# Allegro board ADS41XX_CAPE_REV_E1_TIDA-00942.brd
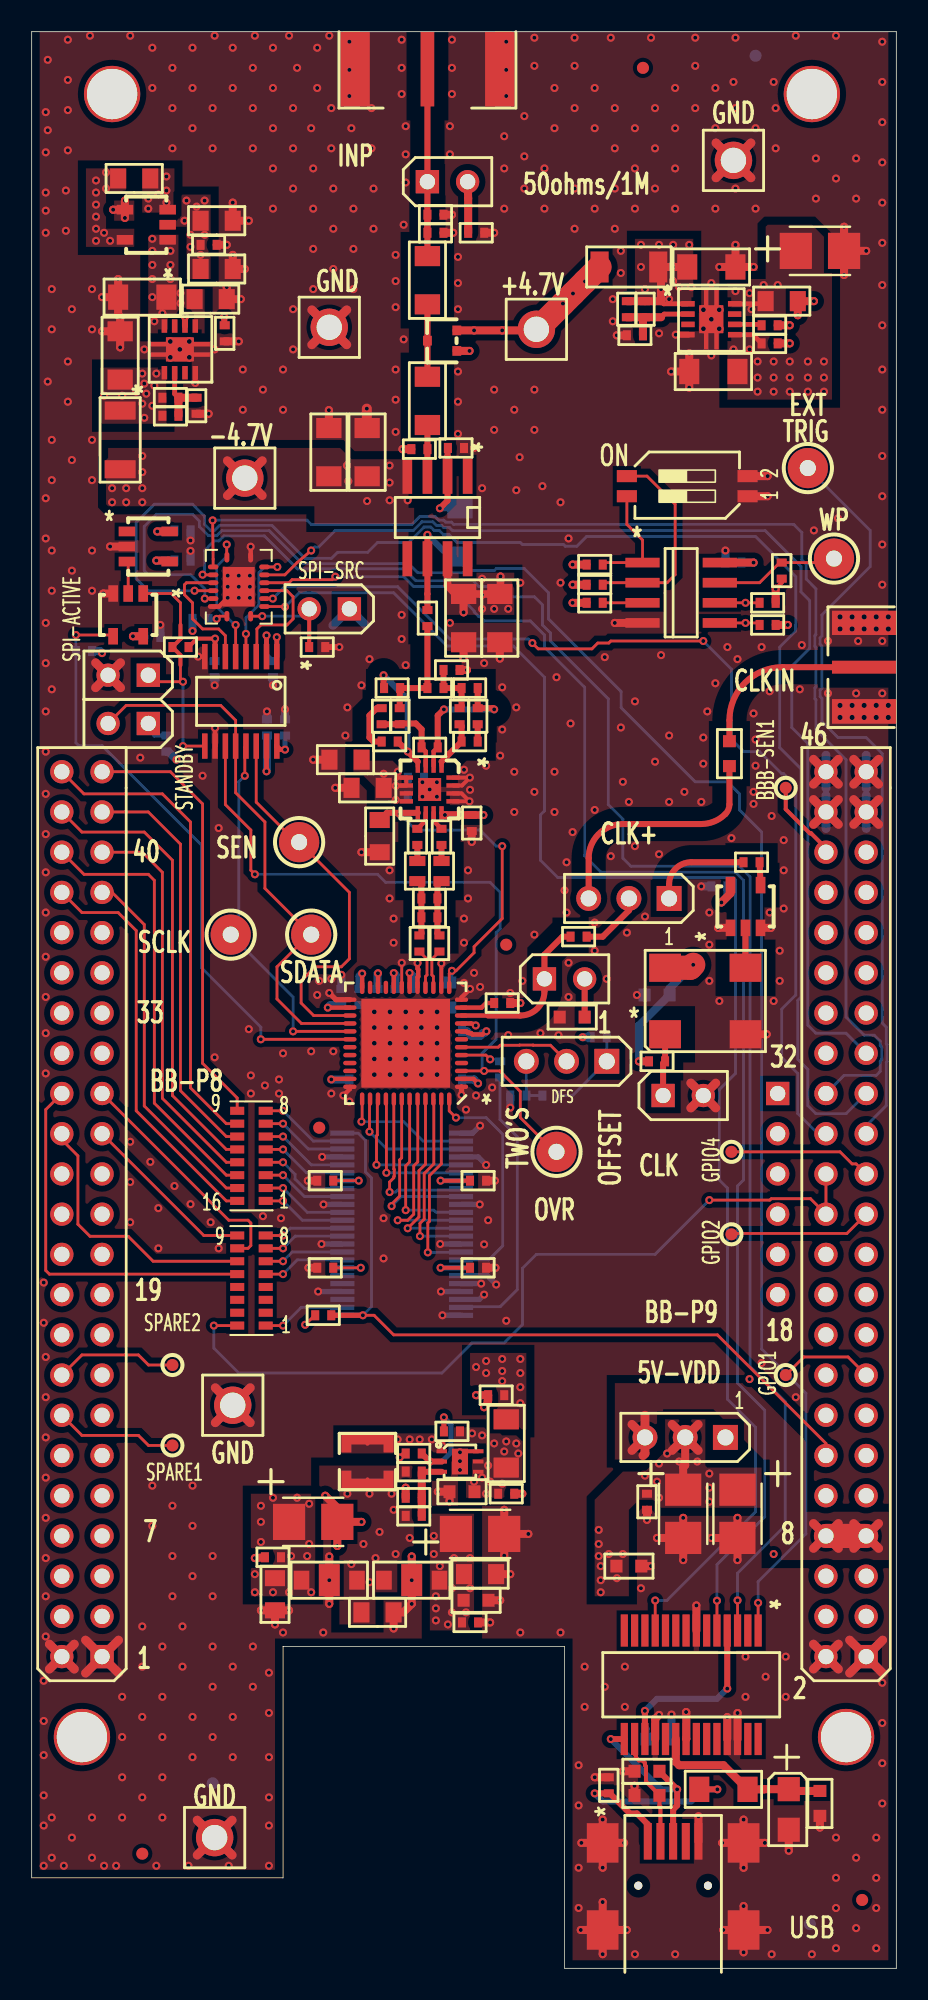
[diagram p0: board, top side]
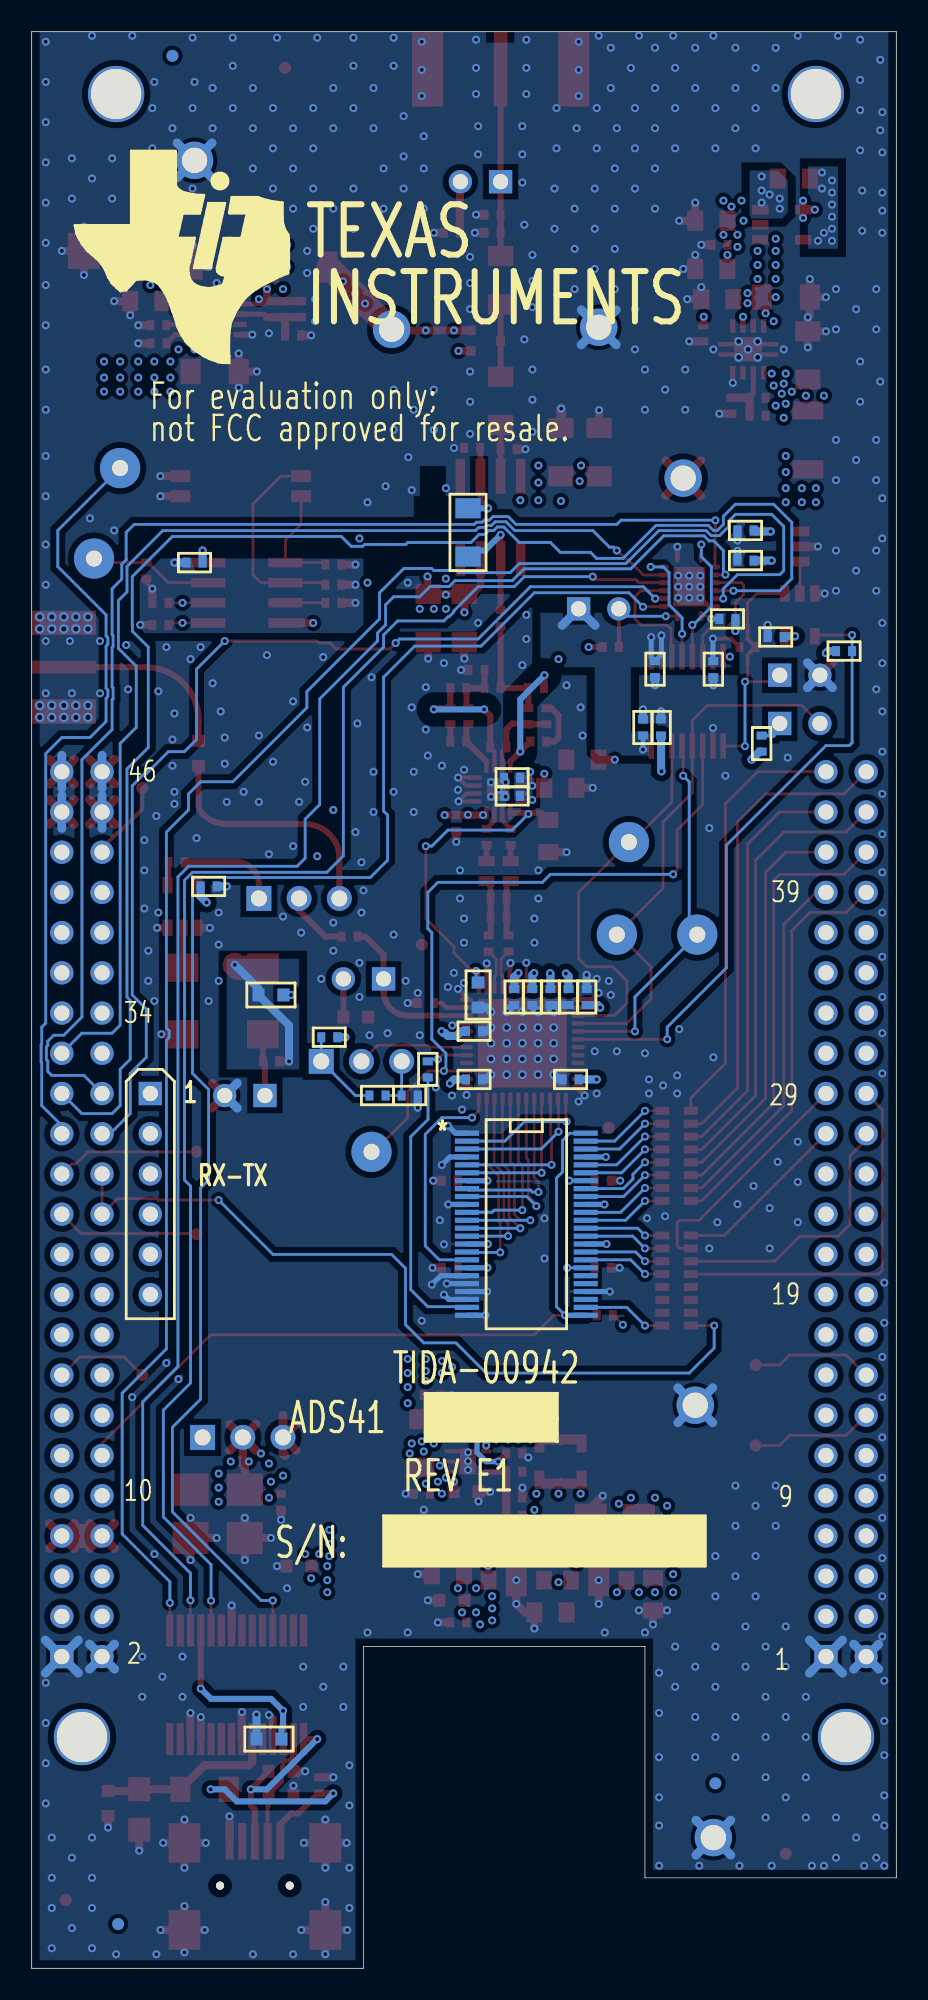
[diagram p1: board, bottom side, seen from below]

Outline 54.61 x 122.3 mm; copper layers: TOP, GND1, PWR1, PWR2, GND2, BOTTOM. Coordinates in mm from the lower left corner of the outline.
Outline path: 0,122.3 0,5.71 15.88,5.71 15.88,20.32 33.66,20.32 33.66,0 54.61,0 54.61,122.3 0,122.3

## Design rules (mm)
net group B: nets B+ B-
net group CLK: nets CLK+ CLK-
net group IN: nets IN_M IN_P
net group PWR: nets N18756762 N18756812

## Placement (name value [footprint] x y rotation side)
C1  82pF  [0402]  25.5 80.85 0 top
C2  12pF  [0402]  28.17 79.07 270 top
C3  5.6pF  [0402]  25.14 77.1 0 top
C4  10uF  [0805]  21.22 74.55 180 top
C5  .1uF  [0805]  19.82 76.33 180 top
C6  .1uF  [0402]  24.27 75.18 0 bottom
C7  .1uF  [0402]  24.27 74.04 0 bottom
C8  .1uF  [0402]  34.54 65.15 180 top
C9  .1uF  [0402]  43.43 68.33 0 bottom
C10  .1uF  [0402]  29.72 60.96 0 top
C11  5pF  [0402]  24.49 95.94 180 top
C12  0.1uF  [0603]  39.5 61.47 180 bottom
C13  .01uF  [0402]  26.67 59.18 180 bottom
C14  .01uF  [0402]  24.13 61.34 270 bottom
C15  .01uF  [0402]  19.56 61.34 90 bottom
C16  .01uF  [0402]  20.7 61.34 270 bottom
C17  .01uF  [0402]  21.84 61.34 270 bottom
C18  .01uF  [0402]  22.99 61.34 270 bottom
C19  .01uF  [0402]  20.57 56.13 0 bottom
C20  .01uF  [0402]  26.67 56.13 180 bottom
C21  0.1uF  [0603]  26.42 61.47 270 bottom
C22  .01uF  [0402]  15.24 82.04 270 bottom
C23  .01uF  [0402]  36.45 11.56 90 top
C24  0.1uF  [0603]  49.78 10.41 270 top
C25  4.7uF  [TANT_A]  47.82 10.03 270 top
C26  47pF  [0603]  38.86 10.92 180 top
C27  47pF  [0603]  38.86 12.45 180 top
C28  0.1uF  [0603]  39.62 14.48 0 bottom
C29  .01uF  [0402]  18.54 44.24 180 top
C30  .01uF  [0402]  18.54 49.74 180 top
C31  .01uF  [0402]  28.19 44.24 0 top
C32  .01uF  [0402]  28.19 49.74 0 top
C33  47uF  [TANT_B]  44.58 28.7 270 top
C34  10uF  [TANT_B]  41.15 28.7 270 top
C35  .1uF  [0402]  38.86 29.46 270 top
C36  1uF  [0603]  37.72 25.4 0 top
C38  .1uF  [0402]  29.34 36.2 180 top
C39  .01uF  [0402]  29.97 29.97 0 top
C40  1uF  [0603]  27.18 30.1 180 top
C41  22pF  [0402]  24.13 28.57 0 top
C42  10uF  [0805]  21.84 22.48 0 top
C43  33uF  [TANT_B]  28.32 27.43 0 top
C44  10uF  [0805]  28.32 24.89 0 top
C45  2.2uF  [0603]  28.07 23.24 0 top
C46  .1uF  [0402]  27.69 21.84 0 top
C48  33uF  [TANT_B]  17.78 28.19 0 top
C49  10uF  [0805]  15.37 23.62 270 top
C50  .1uF  [0402]  15.24 25.96 180 top
C51  .01uF  [0402]  11.56 82.04 270 bottom
C52  10uF  [TANT_B]  49.78 108.46 0 top
C53  .01uF  [0402]  16 78.36 90 bottom
C54  .01uF  [0402]  14.86 78.36 90 bottom
C56  680pF  [0402]  25.12 66.37 0 top
C57  .1uF  [1206]  21.18 95.75 90 top
C58  .1uF  [1206]  27.28 85.27 270 top
C59  6.8uF  [1206]  18.77 95.75 90 top
C60  6.8uF  [1206]  29.57 85.27 270 top
C61  .1uF  [0402]  44.32 88.77 180 bottom
C62  10pF  [0402]  25.5 110.74 0 top
C71  .1uF  [0402]  27.79 72.33 270 top
C75  10uF  [0805]  47.37 105.28 0 top
C76  .1uF  [0402]  46.61 102.62 180 top
C77  10uF  [1206]  43.05 100.84 180 top
C78  10uF  [1206]  42.93 107.44 0 top
C79  .01uF  [0402]  38.73 104.78 270 top
C80  .01uF  [0402]  46.61 103.76 0 top
C82  10uF  [0805]  11.68 107.31 0 top
C83  .1uF  [0402]  11.18 108.84 180 top
C84  1uF  [0805]  11.68 110.36 0 top
C86  10uF  [1206]  6.99 105.54 180 top
C87  10uF  [1206]  5.59 101.85 90 top
C88  .01uF  [0402]  8.76 99.19 0 top
C89  1uF  [0402]  12.19 103.25 270 top
C90  1uF  [0805]  11.3 105.41 0 top
C91  1uF  [0805]  6.48 113.03 0 top
C98  .1uF  [0805]  21.98 71.5 270 top
C99  12pF  [0402]  22.1 79.07 90 top
C101  .01uF  [0402]  10.67 85.22 180 bottom
C102  .01uF  [0402]  7.62 84.07 0 bottom
C103  .1uF  [0402]  9.53 88.9 0 bottom
C104  1uF  [0402]  9.53 90.81 0 bottom
D1  BAV99W  [SOT_323]  25.92 102.79 90 top
FB1  120 OHM @ 100MHz  [1206]  43.69 11.3 0 top
FB3  27uF  [1206_BEAD_NFM31P]  24 24.51 0 top
FB4  27uF  [1206_BEAD_NFM31P]  18.8 24.51 180 top
FB5  120 OHM @ 100MHz  [1206]  29.97 33.15 270 top
FB6  1k @ 100MHz  [1806]  37.72 107.44 0 top
FB7  1k @ 100MHz  [1806]  5.59 96.52 90 top
J1  BNC, HIGH FREQ, END LAUNCH  [BNC_END_LAUNCH_50_OHM_112640]  24.99 122.3 0 top
J2  HDR, THVT, 6POS, .100, FEMALE  [HDR_THVT_1X6_100_M]  47.12 55.24 180 bottom
J3  SMA_END_JACK_RND  [SMA_SMEL_250X215]  54.61 82.17 270 top
J4  USB, MINI_AB  [CON_SMRT_USBMNE20_F]  40.51 4.57 90 top
J5  HDR, THVT, 46POS, .100, FEMALE  [HDR_THVT_2X23_100_M]  4.45 19.68 180 top
J6  HDR, THVT, 46POS, .100, FEMALE  [HDR_THVT_2X23_100_M]  52.7 19.68 180 top
JP1  HEADER, 2POS, .100  [HDR_THVT_1X2_100_M]  7.37 78.61 270 top
JP2  HEADER, 2POS, .100  [HDR_THVT_1X2_100_M]  20.07 85.85 270 top
JP3  HEADER, 2POS, .100  [HDR_THVT_1X2_100_M]  7.37 81.66 270 top
JP4  HEADER, 3POS, .100  [HDR_THVT_1X3_100_M]  43.81 33.53 270 top
JP5  HEADER, 2POS, .100  [HDR_THVT_1X2_100_M]  24.99 112.83 90 top
JP6  HEADER, 3POS, .100  [HDR_THVT_1X3_100_M]  36.32 57.28 270 top
JP7  HEADER, 2POS, .100  [HDR_THVT_1X2_100_M]  39.88 55.12 90 top
JP8  HEADER, 3POS, .100  [HDR_THVT_1X3_100_M]  40.26 67.56 270 top
JP9  HEADER, 2POS, .100  [HDR_THVT_1X2_100_M]  32.38 62.48 90 top
L1  2.2uH  [LPS3015]  21.21 32 270 top
L2  390nH  [IND_0603]  24.36 69.29 270 top
L3  390nH  [IND_0603]  25.88 69.29 270 top
MT1  STANDOFF, FEMALE, 4-40 X 3/4"  [MFG125_PLATED]  5.08 118.36 0 top
MT2  STANDOFF, FEMALE, 4-40 X 3/4"  [MFG125_PLATED]  49.28 118.36 0 top
MT3  STANDOFF, FEMALE, 4-40 X 3/4"  [MFG125_PLATED]  3.17 14.61 0 top
MT4  STANDOFF, FEMALE, 4-40 X 3/4"  [MFG125_PLATED]  51.44 14.61 0 top
NOREF  -  []  54.61 0 90 top
NOREF#2  -  []  15.88 5.71 0 top
NOREF#3  -  []  33.66 0 0 top
NOREF#4  -  [unnamed#2]  18.16 53.09 0 top
NOREF#5  -  []  0 5.71 90 top
NOREF#6  -  []  -52.2 -70.97 0 top
NOREF#7  -  []  0 5.71 0 top
NOREF#8  -  []  475.87 104.42 0 top
NOREF#9  -  [unnamed#2]  38.61 120.02 0 top
NOREF#10  -  [unnamed#2]  29.97 64.64 0 top
NOREF#11  -  []  33.66 0 90 top
NOREF#12  -  [unnamed#2]  6.99 7.24 0 top
NOREF#13  -  []  0 5.71 90 top
NOREF#14  -  [unnamed#2]  52.45 4.32 0 top
NOREF#15  -  []  205.61 62.97 0 top
NOREF#16  -  []  3.17 14.61 0 top
NOREF#17  -  []  54.61 0 90 top
NOREF#18  -  []  33.66 0 90 top
NOREF#19  -  []  51.44 14.61 0 top
NOREF#20  -  []  39.37 26.04 180 bottom
NOREF#21  -  [unnamed#2]  49.15 2.79 180 bottom
NOREF#22  -  []  43.83 108.62 180 bottom
NOREF#23  -  [unnamed#2]  45.72 120.78 180 bottom
NOREF#24  -  []  36.82 33.85 180 bottom
NOREF#25  -  [unnamed#2]  11.43 11.68 180 bottom
NOREF#26  -  []  105.16 78.11 180 bottom
PP1  PROBE POINT  [PROBE_POINT_30PAD]  47.62 37.47 0 top
PP2  PROBE POINT  [PROBE_POINT_30PAD]  44.2 51.56 0 top
PP3  PROBE POINT  [PROBE_POINT_30PAD]  44.2 46.35 0 top
PP4  PROBE POINT  [PROBE_POINT_30PAD]  8.89 38.1 0 top
PP5  PROBE POINT  [PROBE_POINT_30PAD]  8.89 33.02 0 top
PP6  PROBE POINT  [PROBE_POINT_30PAD]  47.62 74.55 0 top
R1  27.4  [0402]  24.36 71.45 270 top
R2  8.25  [0402]  22.61 77.47 0 top
R3  27.4  [0402]  25.88 71.45 270 top
R4  8.25  [0402]  27.66 77.47 180 top
R5  348  [0402]  23.25 79.07 270 top
R6  348  [0402]  27.66 80.85 0 top
R7  221  [0402]  27.03 79.07 270 top
R8  392  [0402]  24.99 85.27 270 top
R9  49.9  [1206]  24.99 98.98 270 top
R10  150  [1206]  24.99 106.6 270 top
R11  392  [0402]  26.52 81.99 0 top
R12  649k  [0402]  8.76 98.04 0 top
R13  215k  [0402]  10.41 98.68 270 top
R14  442  [0402]  25.12 67.56 180 top
R15  5.6k  [0402]  46.48 84.84 180 top
R16  200  [1206]  27.05 90.68 270 bottom
R17  221  [0402]  22.76 80.85 180 top
R18  0  [0603]  44.07 76.71 270 top
R19  2k  [0402]  32.77 55.12 180 bottom
R20  5.6k  [0402]  46.48 86.23 180 top
R21  49.9  [0603]  34.14 60.07 180 top
R22  4.75k  [0402]  35.56 86.23 0 top
R23  4.75k  [0402]  35.56 87.38 0 top
R24  10k  [0402]  39.5 57.28 0 top
R25  49.9  [0402]  45.47 69.85 180 top
R26  4.75k  [0402]  35.56 88.65 0 top
R27  22.1  [0402]  29.59 56.77 90 bottom
R30  3k  [0402]  35.81 58.8 0 bottom
R31  0  [0402]  24.13 32.51 180 top
R32  3k  [0402]  30.73 55.12 180 bottom
R41  4.7k  [0402]  18.41 41.24 0 top
R42  0  [0402]  26.54 33.91 180 top
R44  360k  [0402]  24.13 31.37 0 top
R46  180k  [0402]  24.13 29.72 180 top
R53  5.1  [0402]  24.49 64.72 270 top
R54  5.1  [0402]  25.76 64.72 270 top
R55  49.9  [0402]  28.08 109.6 0 top
R56  1M  [0402]  25.5 109.6 180 top
R57  249  [0402]  26.8 96.01 0 top
R83  34.8k  [0402]  37.59 104.78 270 top
R84  12k  [0402]  38.1 103.12 180 top
R85  10k  [0402]  18.03 83.44 0 top
R86  10k  [0402]  9.4 83.44 180 top
R87  10k  [0402]  8.51 77.34 90 bottom
R88  10k  [0402]  3.3 83.19 180 bottom
R89  10k  [0402]  47.37 88.27 90 top
RN1  22  [RNET8_16_0603]  15.75 52.96 180 top
RN2  22  [RNET8_16_0603]  15.75 45.09 180 top
SW1  SWITCH, ULTRA MINI  [SW_SM_2POS_144X244_50_TDA]  41.4 93.6 90 top
TP3  BLU  [TP_THVT_100_RND]  33.15 51.56 0 top
TP8  BLK  [TP_THVT_125_RND_063D]  11.56 8.26 0 top
TP9  BLK  [TP_THVT_125_RND_063D]  12.7 35.56 0 top
TP10  RED  [TP_THVT_125_RND_063D]  31.88 103.5 0 top
TP11  RED  [TP_THVT_125_RND_063D]  13.46 94.11 0 top
TP12  BLU  [TP_THVT_100_RND]  49.02 94.74 0 top
TP13  BLK  [TP_THVT_125_RND_063D]  44.32 114.17 0 top
TP14  BLK  [TP_THVT_125_RND_063D]  18.8 103.63 0 top
TP15  BLU  [TP_THVT_100_RND]  16.89 71.12 0 top
TP16  BLU  [TP_THVT_100_RND]  12.57 65.28 0 top
TP17  BLU  [TP_THVT_100_RND]  17.65 65.28 0 top
TP18  BLU  [TP_THVT_100_RND]  50.67 89.03 0 top
U1  ADS4122  [QFN_48_281X281_0P50MM_RGZ]  23.62 58.42 180 top
U2  FT245RL  [SSOP_28_413X221_26]  41.66 17.91 270 top
U3  SN74AVC16T245DGGR  [TSSOP_48_496X244_20]  23.37 46.99 180 bottom
U4  TPS62590  [SON_DRV_6]  27.05 32 0 top
U5  THS4541  [VQFN_16_124X124_PWRPAD]  25.14 74.45 270 top
U6  OPA656NB  [SO_8_197X157_50]  25.63 91.62 270 top
U7  TPS7A4901  [SON_8_3MMX3MM_0P65MM]  42.93 104.14 0 top
U8  TPS60403  [SOT-23_5_63X114_DBV]  7.24 110.11 180 top
U9  TPS7A3001  [SON_8_3MMX3MM_0P65MM]  9.36 102.24 90 top
U10  SN74AVC4T774  [TSSOP_16_201X177_26]  13.21 80.01 270 top
U11  SN74CB3Q3257  [VQFN_16_163X144_0P50MM_RGY]  13.08 87.25 270 top
U12  TPS3125J18  [SOT-23_5_63X114_DBV]  7.37 89.79 0 top
U13  SN74AUC1G125  [SOT-23_5_63X114_DBV]  6.1 85.47 270 top
U14  SN74AUC1G125  [SOT-23_5_63X114_DBV]  45.09 67.06 90 top
U15  CAT24C256W  [SOIC_8_197X157_50]  41.02 86.87 0 top
Y1  20.000MHz  [OSC_4_SM_295X197]  42.55 61.09 0 top

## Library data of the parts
C1 = CAP_0402_82pF
C2 C3 C99 = CAP_0402_5.6pF
C4 = CAP_0805_10uF_16V: tolerance: 10%, 10V, X7R
C5 = CAP_0805_.1uF_16V: tolerance: 10%, 50V, X7R
C6 C7 C10 C35 C38 C46 C50 C61 C71 C103 = CAP_0402_0.1uF
C8 C9 = CAP_0402_0.1uF_H
C11 = CAP_0402_5pF
C12 C21 C24 C28 = CAP_0603_0.1uF
C13-C20 C22 C23 C29-C32 C39 C51 C53 C54 C79 C80 C88 C101 C102 = CAP_0402_0.01uF
C25 = CAP_TANT_A_4.7uF
C26 C27 = CAP_0603_47pF
C33 = CAP_TANT_B_47uF
C34 C52 = CAP_TANT_B_10uF_10V: tolerance: 20%
C36 C40 = CAP_0603_1uF
C41 = CAP_0402_22pF
C42 C44 C49 = CAP_0805_10uF_10V
C43 C48 = CAP_TANT_B_33uF
C45 = CAP_0603_2.2uF
C56 = CAP_0402_680pF
C57 C58 = CAP_1206_.1uF
C59 C60 = CAP_1206_6.8uF
C62 = CAP_0402_10pF
C75 C82 = CAP_1206_2.2uF: tolerance: 10%
C76 C83 = CAPACITOR_NP_1: tolerance: 10%
C77 C78 C86 C87 = CAP_1206_10uF
C84 C90 C91 = CAP_0805_1uF_16V: tolerance: 10%, 25V, X5R
C89 C104 = CAP_0402_1uF
C98 = CAP_0805_0.1uF_HF_10V: tolerance: 5%
D1 = DIODE_DUAL_BAV99W
FB1 FB5 = FERRITE_BEAD_1206_120_H
FB3 FB4 = BEAD_NFM31P
FB6 FB7 = FERRITE_BEAD
J1 = BNC_END_LAUNCH_SMT_112640
J2 = HEADER_1x6_100
J3 = TMP_102603
J4 = USB_MINI_AB_MNE20-5G5P10
J5 J6 = HEADER_2x23_100
JP1-JP3 JP5 JP7 JP9 = JUMPER_1X2_100
JP4 JP6 JP8 = JUMPER_1X3_100
L1 = IND1206_0
L2 L3 = IND_0603_H_0
MT1-MT4 = MOUNTING_HOLE
PP1-PP6 = PROBE_POINT_0
R1 R3 = Res_0402_80.6_H
R2 R4 = Res_0402_8.25: tolerance: 1%
R5 R6 = Res_0402_348
R7 R17 = Res_0402_221
R8 R11 = Res_0402_392
R9 = Res_1206_49.9_.1%: tolerance: .1%
R10 = Res_1206_150: tolerance: 1%
R12 = Res_0402_649k
R13 = Res_0402_215k
R14 = Res_0402_442_H
R15 R20 = Res_0402_5.6K
R16 = Res_1206_200_.1%: tolerance: .1%
R18 = Res_0603_Zero_H
R19 = Res_0402_2K
R21 = RES0603: tolerance: 1%
R22 R23 R26 = Res_0402_4.75k
R24 R85-R89 = Res_0402_10k
R25 = Res_0402_49.9_H
R27 = Res_0402_22.1_H
R30 R32 = Res_0402_3k
R31 = Res_0402_Zero_DNI
R41 = Res_0402_4.7k
R42 = Res_0402_Zero
R44 = Res_0402_360K
R46 = Res_0402_180K
R53 R54 = Res_0402_5.1_H
R55 = Res_0402_49.9
R56 = Res_0402_1M_H
R57 = Res_0402_249_.1%: tolerance: .1%
R83 = Res_0402_34.8k: tolerance: .1%
R84 = Res_0402_12k: tolerance: .1%
RN1 RN2 = R-PACK: tolerance: 5%
SW1 = SW_SM_ULTRA_MINI_TDA02H0SB1
TP3 TP12 TP15-TP18 = TESTPOINT_BLUE
TP8 TP9 TP13 TP14 = TESTPOINT_BLK
TP10 TP11 = TESTPOINT_RED
U1 = ADS412X-VQFN
U2 = FT245RL_0
U3 = SN74AVC16T245DGGR_0
U4 = TPS79633DCQ_3
U5 = THS4541_VQFN
U6 = OPA656UB
U7 = TPS7A49
U8 = TPS6040x
U9 = TPS7A30
U10 = SN74AVC4T774
U11 = SN74CB3Q3257
U12 = TPS3125-XX
U13 U14 = SN74AUC1G125
U15 = CAT24C256W
Y1 = OSC_SM_4_FXO-HC73

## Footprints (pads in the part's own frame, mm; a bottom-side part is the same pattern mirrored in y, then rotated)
0402
  rect 0.508x0.635 smd: 1(-0.508,0) 2(0.508,0)
0603
  rect 0.762x0.813 smd: 1(-0.787,0) 2(0.787,0)
0805
  rect 1.016x1.27 smd: 1(-1.016,0) 2(1.016,0)
1206
  rect 1.27x1.6 smd: 1(-1.524,0) 2(1.524,0)
1206_BEAD_NFM31P
  rect 0.991x1.194 smd: 1(-1.753,0) 3(1.753,0)
  rect 1.321x2.032 smd: 2(0,0)
1806
  rect 1.143x1.956 smd: 1(-1.854,0) 2(1.854,0)
BNC_END_LAUNCH_50_OHM_112640
  rect 0.86x4.72 smd: 1(0,-2.36)
  rect 1.35x4.72 smd: 2(-4.925,-2.36) 3(4.925,-2.36)
  rect 1.67x4.72 smd: 4(4.475,-2.36) 5(-4.475,-2.36)
CON_SMRT_USBMNE20_F
  round 0.508 hole 0.991 unplated: (0.65,2.2) (0.65,-2.2)
  rect 2.311x0.508 smd: 1(3.45,1.6) 2(3.45,0.8) 3(3.45,0) 4(3.45,-0.8) 5(3.45,-1.6)
  rect 2.489x2.007 smd: 6(-2.15,-4.45) 7(3.35,-4.45) 8(3.35,4.45) 9(-2.15,4.45)
HDR_THVT_1X2_100_M
  rect 1.473x1.473 hole 0.965: 1(0,0)
  round 1.473 hole 0.965: 2(0,-2.54)
HDR_THVT_1X3_100_M
  rect 1.575x1.575 hole 1.016: 1(0,0)
  round 1.575 hole 1.016: 2(0,-2.54) 3(0,-5.08)
HDR_THVT_1X6_100_M
  rect 1.473x1.473 hole 0.965: 1(0,0)
  round 1.473 hole 0.965: 2(0,-2.54) 3(0,-5.08) 4(0,-7.62) 5(0,-10.16) 6(0,-12.7)
HDR_THVT_2X23_100_M
  rect 1.473x1.473 hole 0.965: 1(0,0)
  round 1.473 hole 0.965: 2(2.54,0) 3(0,-2.54) 4(2.54,-2.54) 5(0,-5.08) 6(2.54,-5.08) 7(0,-7.62) 8(2.54,-7.62) 9(0,-10.16) 10(2.54,-10.16) 11(0,-12.7) 12(2.54,-12.7) 13(0,-15.24) 14(2.54,-15.24) 15(0,-17.78) 16(2.54,-17.78) 17(0,-20.32) 18(2.54,-20.32) 19(0,-22.86) 20(2.54,-22.86) 21(0,-25.4) 22(2.54,-25.4) 23(0,-27.94) 24(2.54,-27.94) 25(0,-30.48) 26(2.54,-30.48) 27(0,-33.02) 28(2.54,-33.02) 29(0,-35.56) 30(2.54,-35.56) 31(0,-38.1) 32(2.54,-38.1) 33(0,-40.64) 34(2.54,-40.64) 35(0,-43.18) 36(2.54,-43.18) 37(0,-45.72) 38(2.54,-45.72) 39(0,-48.26) 40(2.54,-48.26) 41(0,-50.8) 42(2.54,-50.8) 43(0,-53.34) 44(2.54,-53.34) 45(0,-55.88) 46(2.54,-55.88)
IND_0603
  rect 0.635x1.016 smd: 1(-0.635,0) 2(0.635,0)
LPS3015
  custom 0.286x0.286 smd: 1(-1.143,0) 2(1.143,0)
MFG125_PLATED
  round 3.556 hole 3.175: 1(0,0)
OSC_4_SM_295X197
  rect 2.007x1.778 smd: 1(-2.54,-2.101) 2(2.54,-2.101) 3(2.54,2.101) 4(-2.54,2.101)
PROBE_POINT_30PAD
  round 0.762 smd: 1(0,0)
QFN_48_281X281_0P50MM_RGZ
  oval 0.838x0.279 smd: 1(-3.526,2.751) 2(-3.526,2.25) 3(-3.526,1.75) 4(-3.526,1.25) 5(-3.526,0.749) 6(-3.526,0.249) 7(-3.526,-0.249) 8(-3.526,-0.749) 9(-3.526,-1.25) 10(-3.526,-1.75) 11(-3.526,-2.25) 12(-3.526,-2.751) 25(3.526,-2.751) 26(3.526,-2.25) 27(3.526,-1.75) 28(3.526,-1.25) 29(3.526,-0.749) 30(3.526,-0.249) 31(3.526,0.249) 32(3.526,0.749) 33(3.526,1.25) 34(3.526,1.75) 35(3.526,2.25) 36(3.526,2.751)
  oval 0.279x0.838 smd: 13(-2.751,-3.526) 14(-2.25,-3.526) 15(-1.75,-3.526) 16(-1.25,-3.526) 17(-0.749,-3.526) 18(-0.249,-3.526) 19(0.249,-3.526) 20(0.749,-3.526) 21(1.25,-3.526) 22(1.75,-3.526) 23(2.25,-3.526) 24(2.751,-3.526) 37(2.751,3.526) 38(2.25,3.526) 39(1.75,3.526) 40(1.25,3.526) 41(0.749,3.526) 42(0.249,3.526) 43(-0.249,3.526) 44(-0.749,3.526) 45(-1.25,3.526) 46(-1.75,3.526) 47(-2.25,3.526) 48(-2.751,3.526)
  rect 5.601x5.601 smd: 49(0,0)
RNET8_16_0603
  rect 0.889x0.508 smd: 1(0.965,4.496) 2(0.965,3.683) 3(0.965,2.87) 4(0.965,2.057) 5(0.965,1.245) 6(0.965,0.432) 7(0.965,-0.381) 8(0.965,-1.194) 9(2.769,-1.194) 10(2.769,-0.381) 11(2.769,0.432) 12(2.769,1.245) 13(2.769,2.057) 14(2.769,2.87) 15(2.769,3.683) 16(2.769,4.496)
SMA_SMEL_250X215
  rect 0.813x4.064 smd: 1(0,-2.032)
  rect 1.524x4.064 smd: 2(-2.794,-2.032) 3(2.794,-2.032) 4(-2.794,-2.032) 5(2.794,-2.032)
SO_8_197X157_50
  rect 2.21x0.61 smd: 1(-2.603,1.905) 2(-2.603,0.635) 3(-2.603,-0.635) 4(-2.603,-1.905) 5(2.603,-1.905) 6(2.603,-0.635) 7(2.603,0.635) 8(2.603,1.905)
SOIC_8_197X157_50
  rect 2.159x0.61 smd: 1(-2.44,1.905) 2(-2.44,0.635) 3(-2.44,-0.635) 4(-2.44,-1.905) 5(2.44,-1.905) 6(2.44,-0.635) 7(2.44,0.635) 8(2.44,1.905)
SON_8_3MMX3MM_0P65MM
  rect 0.85x0.35 smd: 1(-1.475,0.975) 2(-1.475,0.325) 3(-1.475,-0.325) 4(-1.475,-0.975) 5(1.475,-0.975) 6(1.475,-0.325) 7(1.475,0.325) 8(1.475,0.975)
  rect 1.5x1.75 smd: 9(0,0)
SON_DRV_6
  rect 0.66x0.254 smd: 1(-1.152,0.65) 2(-1.152,0) 3(-1.152,-0.65) 4(1.152,-0.65) 5(1.152,0) 6(1.152,0.65)
  rect 1.016x1.626 smd: 7(0,0)
SOT-23_5_63X114_DBV
  rect 1.041x0.61 smd: 1(-1.35,0.95) 2(-1.35,0) 3(-1.35,-0.95) 4(1.35,-0.95) 5(1.35,0.95)
SOT_323
  rect 0.61x0.559 smd: 1(-0.648,-0.927) 2(0.648,-0.927) 3(0,0.927)
SSOP_28_413X221_26
  rect 2.032x0.457 smd: 1(-3.425,4.225) 2(-3.425,3.575) 3(-3.425,2.925) 4(-3.425,2.275) 5(-3.425,1.625) 6(-3.425,0.975) 7(-3.425,0.325) 8(-3.425,-0.325) 9(-3.425,-0.975) 10(-3.425,-1.625) 11(-3.425,-2.275) 12(-3.425,-2.925) 13(-3.425,-3.575) 14(-3.425,-4.225) 15(3.425,-4.225) 16(3.425,-3.575) 17(3.425,-2.925) 18(3.425,-2.275) 19(3.425,-1.625) 20(3.425,-0.975) 21(3.425,-0.325) 22(3.425,0.325) 23(3.425,0.975) 24(3.425,1.625) 25(3.425,2.275) 26(3.425,2.925) 27(3.425,3.575) 28(3.425,4.225)
SW_SM_2POS_144X244_50_TDA
  rect 0.762x1.27 smd: 1(-0.635,-3.81) 2(0.635,-3.81) 3(0.635,3.81) 4(-0.635,3.81)
TANT_A
  rect 1.524x1.397 smd: 1(-1.283,0) 2(1.283,0)
TANT_B
  rect 2.032x2.286 smd: 1(-1.524,0) 2(1.524,0)
TP_THVT_100_RND
  round 2.54 hole 1.016: 1(0,0)
TP_THVT_125_RND_063D
  round 2.362 hole 1.6: 1(0,0)
TSSOP_16_201X177_26
  rect 1.6x0.35 smd: 1(-2.825,2.275) 2(-2.825,1.625) 3(-2.825,0.975) 4(-2.825,0.325) 5(-2.825,-0.325) 6(-2.825,-0.975) 7(-2.825,-1.625) 8(-2.825,-2.275) 9(2.825,-2.275) 10(2.825,-1.625) 11(2.825,-0.975) 12(2.825,-0.325) 13(2.825,0.325) 14(2.825,0.975) 15(2.825,1.625) 16(2.825,2.275)
TSSOP_48_496X244_20
  rect 1.524x0.33 smd: 1(-3.75,5.75) 2(-3.75,5.25) 3(-3.75,4.75) 4(-3.75,4.25) 5(-3.75,3.75) 6(-3.75,3.25) 7(-3.75,2.75) 8(-3.75,2.25) 9(-3.75,1.75) 10(-3.75,1.25) 11(-3.75,0.75) 12(-3.75,0.25) 13(-3.75,-0.25) 14(-3.75,-0.75) 15(-3.75,-1.25) 16(-3.75,-1.75) 17(-3.75,-2.25) 18(-3.75,-2.75) 19(-3.75,-3.25) 20(-3.75,-3.75) 21(-3.75,-4.25) 22(-3.75,-4.75) 23(-3.75,-5.25) 24(-3.75,-5.75) 25(3.75,-5.75) 26(3.75,-5.25) 27(3.75,-4.75) 28(3.75,-4.25) 29(3.75,-3.75) 30(3.75,-3.25) 31(3.75,-2.75) 32(3.75,-2.25) 33(3.75,-1.75) 34(3.75,-1.25) 35(3.75,-0.75) 36(3.75,-0.25) 37(3.75,0.25) 38(3.75,0.75) 39(3.75,1.25) 40(3.75,1.75) 41(3.75,2.25) 42(3.75,2.75) 43(3.75,3.25) 44(3.75,3.75) 45(3.75,4.25) 46(3.75,4.75) 47(3.75,5.25) 48(3.75,5.75)
unnamed#2
  round 0.762 smd: (0,0)
VQFN_16_124X124_PWRPAD
  rect 0.838x0.279 smd: 1(-1.473,0.749) 2(-1.473,0.249) 3(-1.473,-0.249) 4(-1.473,-0.749) 9(1.473,-0.749) 10(1.473,-0.249) 11(1.473,0.249) 12(1.473,0.749)
  rect 0.279x0.838 smd: 5(-0.749,-1.473) 6(-0.249,-1.473) 7(0.249,-1.473) 8(0.749,-1.473) 13(0.749,1.473) 14(0.249,1.473) 15(-0.249,1.473) 16(-0.749,1.473)
  rect 1.448x1.448 smd: 17(0,0)
VQFN_16_163X144_0P50MM_RGY
  oval 0.66x0.305 smd: 1(1.861,0.75) 8(-1.861,0.75) 9(-1.861,-0.75) 16(1.861,-0.75)
  oval 0.305x0.66 smd: 2(1.25,1.62) 3(0.75,1.62) 4(0.25,1.62) 5(-0.25,1.62) 6(-0.75,1.62) 7(-1.25,1.62) 10(-1.25,-1.62) 11(-0.75,-1.62) 12(-0.25,-1.62) 13(0.25,-1.62) 14(0.75,-1.62) 15(1.25,-1.62)
  rect 2.489x2.007 smd: 17(0,0)

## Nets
1.8V: L1.1 U4.1(SW)
1.8V_IN: C41.1 C42.1 FB3.1 FB4.1 L1.2 R44.1
5V_IN: C39.1 C40.1 FB5.2 R42.1 U4.4(EN) U4.5(IN)
+1.8VA: C13.1 C14.1 C15.1 C16.1 C17.1 C18.1 C43.1 C44.1 C45.1 C46.1 FB3.3 R30.1 U1.8(AVDD#8) U1.18(AVDD#18) U1.20(AVDD#20) U1.22(AVDD#22) U1.24(AVDD#24) U1.26(AVDD#26)
+1.8VD: C9.2 C19.1 C20.1 C31.1 C32.1 C48.1 C49.1 C50.1 C54.1 C102.1 C103.1 C104.1 FB4.3 R87.1 R88.1 U1.2(DRVDD#2) U1.35(DRVDD#35) U3.7(VCCB#7) U3.18(VCCB#18) U10.15(VCCB) U12.4(M\R\) U12.5(VDD) U13.5(VCC) U14.5(VCC)
+3.3V: C12.1 C22.1 C29.1 C30.1 C51.1 C53.1 C61.1 C101.1 J6.3 J6.4 JP2.1 R15.1 R20.1 R22.1 R23.1 R24.1 R26.1 R41.1 R86.1 R89.1 U3.31(VCCA#31) U3.42(VCCA#42) U10.1(DIR1) U10.2(DIR2) U10.7(DIR3) U10.16(VCCA) U11.16(VCC) U15.8(VCC) Y1.4(VDD)
+4.7V: C4.1 C5.1 C6.1 C7.1 C58.1 C60.1 C71.1 D1.2 FB6.1 TP10.1(TP) U5.5(VS+#5) U5.6(VS+#6) U5.7(VS+#7) U5.8(VS+#8) U5.12(\\P\D\) U6.7(+VS)
+5V: C33.1 C34.1 C35.1 C36.1 C38.1 C52.1 C75.1 C76.2 C77.1 C82.1 C83.2 C84.1 FB5.1 JP4.2(PIN2) U7.5(EN) U7.8(IN) U8.2(IN)
-4.7V: C57.1 C59.1 D1.1 FB7.1 TP11.1(TP) U6.4(-VS)
-5V: C86.1 C90.1 U8.1(OUT) U9.5(EN) U9.8(IN)
GND: C4.2 C5.2 C6.2 C7.2 C9.1 C10.2 C11.2 C12.2 C13.2 C14.2 C15.2 C16.2 C17.2 C18.2 C19.2 C20.2 C21.2 C22.2 C23.2 C24.2 C25.2 C26.2 C27.2 C28.2 C29.2 C30.2 C31.2 C32.2 C33.2 C34.2 C35.2 C36.2 C38.2 C39.2 C40.2 C42.2 C43.2 C44.2 C45.2 C46.2 C48.2 C49.2 C50.2 C51.2 C52.2 C53.2 C54.2 C57.2 C58.2 C59.2 C60.2 C61.2 C62.2 C71.2 C75.2 C76.1 C77.2 C78.2 C80.2 C82.2 C83.1 C84.2 C86.2 C87.2 C89.2 C90.2 C98.2 C101.2 C102.2 C103.2 C104.2 FB3.2 FB4.2 J1.2(SHIELD2) J1.3(SHIELD3) J1.4(SHIELD4) J1.5(SHIELD5) J3.2(GND#2) J3.3(GND#3) J3.4(GND#4) J3.5(GND#5) J4.5(GND) J4.6(GND1) J4.7(GND2) J4.8(GND3) J4.9(GND4) J5.1 J5.2 J6.1 J6.2 J6.43 J6.44 J6.45 J6.46 JP3.2 JP7.2 R11.2 R13.2 R21.2 R31.2 R32.2 R46.2 R55.2 R56.1 R57.2 R84.2 R85.2 SW1.1(A1) SW1.2(A2) TP8.1(TP) TP9.1(TP) TP13.1(TP) TP14.1(TP) U1.1(DRGND#1) U1.9(AGND#9) U1.12(AGND#12) U1.14(AGND#14) U1.17(AGND#17) U1.19(AGND#19) U1.25(AGND#25) U1.36(DRGND#36) U1.49(GND) U2.7(GND#7) U2.18(GND#18) U2.21(GND#21) U2.25(AGND) U2.26(TEST) U3.1(1DIR) U3.4(GND1) U3.10(GND2) U3.15(GND3) U3.19(2B5) U3.20(2B6) U3.21(GND4) U3.22(2B7) U3.24(2DIR) U3.28(GND5) U3.34(GND6) U3.39(GND7) U3.45(GND8) U4.6(GND) U4.7(THERMPAD) U5.13(VS-#13) U5.14(VS-#14) U5.15(VS-#15) U5.16(VS-#16) U5.17(PWRPAD) U7.4(GND) U7.9(TPAD) U8.4(GND) U9.4(GND) U9.9(TPAD) U10.8(DIR4) U10.10(GND) U11.8(GND) U11.15(O\E\) U11.17(PAD) U12.2(GND) U13.3(GND) U14.1(\\O\E\) U14.3(GND) U15.4(VSS) Y1.2(GND)
P4.7V: C78.1 C79.1 FB6.2 R83.1 U7.1(OUT)
VDD_5V: J6.5 J6.6 JP4.1(PIN1)
VIN-: R16.1 R57.1 U6.2(INV-IN)
AIN_P: C11.1 R9.2 U6.3(NON-IN)
AINP: C62.1 J1.1(CENTER) JP5.1 R10.1 R56.2
AVP: D1.3 R9.1 R10.2
B+: R1.1 U5.10(OUT+)
B-: R3.1 U5.11(OUT-)
BBB-CLKOUT: J6.24 J6.26 RN2.16(R1_2)
BBB-D0: J5.45 RN1.9(R8_2)
BBB-D1: J5.46 RN1.10(R7_2)
BBB-D2: J5.43 RN1.11(R6_2)
BBB-D3: J5.44 RN1.12(R5_2)
BBB-D4: J5.41 RN1.13(R4_2)
BBB-D5: J5.42 RN1.14(R3_2)
BBB-D6: J5.39 RN1.15(R2_2)
BBB-D7: J5.40 RN1.16(R1_2)
BBB-D8: J5.27 RN2.9(R8_2)
BBB-D9: J5.29 RN2.10(R7_2)
BBB-D10: J5.28 RN2.11(R6_2)
BBB-D11: J5.30 RN2.12(R5_2)
BBB-SCLK: J6.31 U11.6(2B2)
BBB-SDATA: J6.30 U11.10(3B2)
BBB-SDOUT: J6.29 U11.13(4B2)
BBB-SEN: J6.28 U11.3(1B2)
CLK: R25.1 U14.4(Y)
CLK+: C8.2 JP9.1 U1.10(CLKP)
CLK-: C10.1 U1.11(CLKM)
CLK_P: U14.2(A) Y1.3(OUT)
CLKOUT: R27.1 U3.23(2B8)
CLOCK: JP7.1 R24.2 Y1.1(EN)
CLOCKIN: J3.1(CENTER) R18.1
CN: JP8.3(PIN3) R18.2
CP: JP8.1(PIN1) R25.2
D0: U1.37(D0) U3.2(1B1)
D1: U1.38(D1) U3.3(1B2)
D2: U1.39(D2) U3.5(1B3)
D3: U1.40(D3) U3.6(1B4)
D4: U1.41(D4) U3.8(1B5)
D5: U1.42(D5) U3.9(1B6)
D6: U1.43(D6) U3.11(1B7)
D7: U1.44(D7) U3.12(1B8)
D8: U1.45(D8) U3.13(2B1)
D9: U1.46(D9) U3.14(2B2)
D10: U1.47(D10) U3.16(2B3)
D11: U1.48(D11) U3.17(2B4)
DATA_OE: J6.12 R41.2 U3.25(2O\E\) U3.48(1O\E\)
DBIN+: L2.1 R1.2
DBIN-: L3.1 R3.2
DBIN_N: C56.2 L3.2 R14.1 R54.1
DBIN_P: C56.1 L2.2 R14.2 R53.1
DFS: JP6.2(PIN2) U1.6(DFS)
I2C2_SCL: J6.19 R20.2 U15.6(SCL)
I2C2_SDA: J6.20 R15.2 U15.5(SDA)
IN+: C2.1 C3.2 R6.2 U5.2(IN+)
IN-: C3.1 C99.1 R5.2 U5.3(IN-)
IN_M: R53.2 U1.16(INM)
IN_P: R54.2 U1.15(INP)
INM: C1.2 R6.1 R7.1 R11.1
INP: C1.1 R5.1 R8.2 R17.1
N4.7V: C87.1 C88.1 FB7.2 R12.1 U9.1(OUT)
OUT+: R8.1 R16.2 U6.6(OUT)
OVR/SDOUT: TP3.1(TP) U1.3(OVR / SDOUT) U10.11(B4)
RESET: R88.2 U1.30(RESET) U13.4(Y)
SCLK: TP16.1(TP) U1.29(SCLK) U10.13(B2)
SDATA: JP1.2 TP17.1(TP) U1.28(SDATA) U10.12(B3)
SEN: TP15.1(TP) U1.27(SEN) U10.14(B1)
SPARE1: J5.14 PP5.1
SPARE2: J5.16 PP4.1
SPI-ACT: JP3.1 R86.2 U10.9(OEB) U13.1(\\O\E\)
SW1_A0: R26.2 SW1.4(B1) U15.1(A0)
SW1_A1: R23.2 SW1.3(B2) U15.2(A1)
SW1_A2: R22.2 U15.3(A2)
SYS_5V: J6.7 J6.8 JP4.3(PIN3)
USB-SCLK: U2.5(D1) U11.5(2B1)
USB-SDATA: U2.3(D2) U11.11(3B1)
USB-SDOUT: U2.1(D0) U11.14(4B1)
USB-SEN: U2.11(D3) U11.2(1B1)
VCM: C21.1 C98.1 U1.13(VCM) U5.9(VOCM)
N10245644: R27.2 U1.5(CLKOUT)
N18756746: C26.1 J4.2(D-) U2.16(USBDM)
N18756762: C24.1 C25.1 FB1.2 U2.20(VCC)
N18756792: C28.1 U2.4(VCCIO) U2.17(3V3OUT)
N18756806: C27.1 J4.3(D+) U2.15(USBDP)
N18756812: C23.1 FB1.1 J4.1(VBUS)
N18789804: C41.2 R44.2 R46.1 U4.3(FB)
N19612134: RN2.6(R6_1) U3.33(2A3)
N19612140: RN2.7(R7_1) U3.35(2A2)
N19612162: RN2.8(R8_1) U3.36(2A1)
N19612190: RN2.5(R1) U3.32(2A4)
N19612194: RN1.4(R4_1) U3.41(1A5)
N19612196: RN1.1(R1_1) U3.37(1A8)
N19612206: RN2.1(R1_1) U3.26(2A8)
N19612209: RN1.5(R1) U3.43(1A4)
N19612211: RN1.2(R2_1) U3.38(1A7)
N19612213: RN1.8(R8_1) U3.47(1A1)
N19612215: RN1.3(R3_1) U3.40(1A6)
N19612245: RN1.6(R6_1) U3.44(1A3)
N19612247: RN1.7(R7_1) U3.46(1A2)
N19618490: R31.1 R42.2 U4.2(MODE)
N19665097: JP5.2 R55.1
N19665330: R2.2 R17.2 U5.4(FB+)
N19665334: R4.2 R7.2 U5.1(FB-)
N19665338: C2.2 R4.1
N19665444: C99.2 R2.1
N19669855: C80.1 U7.6(NR/SS)
N19669869: C79.2 R83.2 R84.1 U7.2(FB)
N19670052: C91.1 U8.5(CFLY+)
N19670056: C91.2 U8.3(CFLY-)
N19670132: C89.1 U9.6(NR/SS)
N19670140: C88.2 R12.2 R13.1 U9.2(FB)
N19683672: JP6.1(PIN1) R19.1 R30.2
N19683688: JP6.3(PIN3) R19.2 R32.1
N19720857: J6.27 TP12.1(TP)
N19728178: U10.4(A2) U11.7(2A)
N19728180: U10.3(A1) U11.4(1A)
N19728186: U10.5(A3) U11.9(3A)
N19728192: U10.6(A4) U11.12(4A)
N19728318: JP2.2 R85.1 U11.1(S)
N19728429: JP1.1 R87.2
N19730220: J6.42 PP6.1
N19734626: J6.15 PP1.1
N19735928: J6.23 PP3.1
N19735933: J6.25 PP2.1
N19737902: C8.1 JP8.2(PIN2)
N19738595: U12.3(RESET) U13.2(A)
N19746144: R89.2 TP18.1(TP) U15.7(WP)
N19757494: JP9.2 R21.1

Pads without a net: J2 1 2 3 4 5 6; J4 4; J5 3 4 5 6 7 8 9 10 11 12 13 15 17 18 19 20 21 22 23 24 25 26 31 32 33 34 35 36 37 38; J6 9 10 11 13 14 16 17 18 21 22 32 33 34 35 36 37 38 39 40 41; MT1 1; MT2 1; MT3 1; MT4 1; RN2 2 3 4 13 14 15; U1 4 7 21 23 31 32 33 34; U2 2 6 8 9 10 12 13 14 19 22 23 24 27 28; U3 27 29 30; U6 1 5 8; U7 3 7; U9 3 7; U12 1

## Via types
v1: diameter 0.508, hole 0.254, TOP to BOTTOM, 969 vias
v2: diameter 0.559, hole 0.305, TOP to BOTTOM, 35 vias
v3: diameter 0.61, hole 0.33, TOP to BOTTOM, 20 vias

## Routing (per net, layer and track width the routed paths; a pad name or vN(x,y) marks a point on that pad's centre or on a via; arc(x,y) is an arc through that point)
1.8V:
  vias: v1(23.11,33.4) v1(23.88,33.4) v1(24.51,33.4) v1(25.27,33.4) v1(25.91,33.02)
1.8V_IN:
  vias: v1(19.94,29.97) v1(20.19,25.53) v1(20.95,26.8) v1(21.34,29.97) v1(21.34,24.38) v1(21.72,25.91) v1(21.97,27.56) v1(22.73,29.97) v1(22.86,28.96) v1(22.99,26.16) v1(23.88,27.18)
5V_IN:
  vias: v1(27.81,33.78) v1(27.94,30.73) v1(28.45,33.66) v1(28.45,30.99) v1(28.7,29.97) v1(28.83,31.75) v1(28.96,30.73) v1(29.21,33.15) v1(29.72,30.61) v1(29.84,32.64) v1(29.97,33.27) v1(30.61,33.15) v1(30.73,32.51)
+1.8VA: length 14.1
  TOP w0.279: U1.24 v1(20.87,62.82) ; U1.26 v1(18.7,60.67) ; v1(28.72,59.17) 28.47,58.97 27.85,58.97 27.76,59.05 27.65,59.05 27.61,59.1 27.51,59.1 27.44,59.17 U1.8 ; U1.18 v1(23.87,62.86) ; U1.22 v1(21.87,62.84) ; U1.20 v1(22.87,62.85)
  BOTTOM w0.508: 20.7,61.85 20.7,62.65 v1(20.87,62.82) ; v1(23.87,62.86) 24.13,62.6 24.13,61.85 ; v1(22.87,62.85) 22.99,62.74 22.99,61.85 ; C15.1 18.87,60.83 v1(18.7,60.67) ; v1(28.72,59.17) 28.57,59.05 28.49,59.05 28.32,58.88 27.77,58.88 27.47,59.18 C13.1 ; 21.84,61.85 21.84,62.81 v1(21.87,62.84) ; R30.1 v1(34.8,58.8)
  vias: v1(25.4,27.3) v1(25.4,26.16) v1(25.53,23.5) v1(25.53,22.73) v1(25.53,21.97) v1(25.78,25.4) v1(26.29,21.72) v1(26.54,24) v1(26.54,22.48) v1(26.67,25.91) v1(27.43,22.48) v1(27.69,25.91) v1(27.69,24)
+1.8VD: length 24.1
  TOP w0.254: C32.1 v1(25.82,49.74) ; C31.1 v1(25.82,44.24)
  TOP w0.279: v1(28.19,55.88) 27.9,56.17 U1.2 ; v1(18.92,56.13) 18.96,56.17 U1.35
  TOP w0.305: U10.15 v1(14.83,75.59)
  TOP w0.508: v1(43.56,67.31) 44.14,67.88 U14.5 ; v1(7.87,88.9) 8.66,88.9 U12.4 ; U13.5 v1(6.4,84.12) ; U12.5 v1(7.93,90.74)
  BOTTOM w0.33: U3.18 v1(25.82,44.24) ; U3.7 v1(25.82,49.74)
  BOTTOM w0.508: C104.1 8.95,90.74 v1(7.93,90.74) ; C19.1 v1(18.92,56.13) ; C9.2 43.94,67.69 v1(43.56,67.31) ; v1(6.4,84.12) 7.07,84.12 C102.1 ; v1(9.14,76.33) 8.64,76.83 R87.1 ; R88.1 4.32,83.19 v1(4.45,83.06) ; C103.1 v1(7.87,88.9) ; v1(28.19,55.88) 27.94,56.13 C20.1 ; C54.1 14.86,75.62 v1(14.83,75.59)
  vias: v1(14.1,24.89) v1(14.1,23.75) v1(14.48,29.21) v1(14.48,28.19) v1(14.48,26.92) v1(15.24,29.72) v1(15.24,23.75) v1(16.26,23.75) v1(16.38,26.04) v1(16.76,29.72) v1(17.4,26.04) v1(17.53,29.34) v1(17.53,26.8) v1(17.65,23.75)
+3.3V: length 58.4
  TOP w0.178: C30.1 v1(20.66,49.74) ; v1(11.68,85.22) 11.85,85.39 U11.16 ; R41.1 17.87,41.24 v1(17.27,40.64) ; C29.1 v1(20.78,44.24)
  TOP w0.254: v1(46.99,87.12) 47.37,87.5 R89.1 ; R86.1 10.44,83.97 v1(11.58,83.97)
  TOP w0.305: U10.16 15.71,76.96 v1(16,76.96) ; U10.2 v1(14.83,84.18) ; U10.7 v1(11.58,83.97) ; U10.1 v1(15.48,84.06)
  TOP w0.508: R20.1 v1(46.99,87.12) ; U15.8 v1(45.59,88.77) ; R22.1 v1(34.16,86.23) ; R24.1 v1(38.35,57.28) ; R15.1 v1(47.75,84.84) ; R23.1 v1(34.16,87.38) ; R26.1 v1(34.16,88.65)
  TOP w1.524: Y1.4 41.6,63.19 v1(41.78,63.37)
  PWR1 w0.559: J6.3 53.49,23.01 ; J6.3 53.49,21.44 ; J6.3 51.92,21.44 ; J6.3 51.92,23.01 ; J6.4 50.95,21.44 ; J6.4 50.95,23.01 ; J6.4 49.38,23.01 ; J6.4 49.38,21.44 ; 19.28,86.64 JP2.1 ; JP2.1 19.28,85.06 ; JP2.1 20.85,85.06 ; JP2.1 20.85,86.64
  PWR2 w0.559: JP2.1 20.85,85.06 ; JP2.1 19.28,85.06 ; JP2.1 19.28,86.64 ; JP2.1 20.85,86.64
  BOTTOM w0.178: U3.42 v1(20.66,49.74) ; v1(11.68,85.22) C101.1 ; U3.31 v1(20.78,44.24)
  BOTTOM w0.305: v1(15.48,84.06) 15.48,82.79 C22.1 14.83,82.96 v1(14.83,84.18) ; C53.1 v1(16,76.96) ; C51.1 11.58,82.58 v1(11.58,83.97)
  BOTTOM w0.508: C61.1 v1(45.59,88.77) ; v1(38.35,57.28) 38.35,59.54 C12.1 40.28,61.87 v1(41.78,63.37)
  BOTTOM w0.559: 21.11,84.81 JP2.1 19.02,84.81
+4.7V: length 29.1
  TOP w0.254: v1(23,74.68) 23.01,74.69 U5.6 U5.5 23.13,75.2 22.99,75.06
  TOP w0.305: v1(26.1,72.83) 26.02,72.83 U5.12
  TOP w0.483: U6.7 26.26,87.32 26.73,86.83 C58.1 C60.1 29.61,86.83 v1(29.61,87.9) ; v1(26.1,72.83) C71.1 27.8,72.83 v1(28.53,72.83)
  TOP w0.508: C58.1 v1(27.28,85.63) ; D1.2 v1(27.94,103.44) v1(29.72,103.44) 31.81,103.44 TP10.1
  TOP w1.524: FB6.1 v1(34.95,106.53) v1(34.19,105.77) v1(33.55,105.13) 31.86,103.44 31.81,103.44
  PWR1 w0.559: 30.78,102.4 TP10.1 ; TP10.1 32.98,102.4 ; TP10.1 32.98,104.61 ; TP10.1 30.78,104.61
  vias: v1(22.23,75.44) v1(23,73.79) v1(23.12,75.56) v1(27.05,72.85) v1(28.45,87.76) v1(28.45,86.74) v1(28.45,85.85) v1(29.21,85.85) v1(30.1,85.85)
+5V: length 16.6
  TOP w0.305: C76.2 45.55,103.16 U7.5 ; C75.1 46.19,105.12 U7.8
  TOP w0.508: C34.1 41.15,31.65 41.27,31.78 JP4.2
  TOP w0.559: 40.45,34.35 JP4.2 ; JP4.2 42.1,32.7 ; JP4.2 40.45,32.7 ; JP4.2 42.1,34.35
  PWR1 w0.559: JP4.2 42.1,32.7 ; JP4.2 40.45,32.7 ; JP4.2 42.1,34.35 ; JP4.2 40.45,34.35
  vias: v1(9.65,110.36) v1(9.78,111.63) v1(10.03,109.47) v1(10.03,108.71) v1(10.41,111.25) v1(10.67,108.2) v1(10.92,111.63) v1(10.92,109.47) v1(28.07,37.97) v1(28.7,38.35) v1(28.7,37.59) v1(29.72,38.48) v1(29.72,37.72) v1(29.72,37.08) v1(30.86,38.48) v1(30.86,37.59) v1(30.86,36.7) v1(30.86,35.69) v1(35.81,27.69) v1(35.81,26.8) v1(35.81,26.04) v1(35.94,25.4) v1(35.94,24.51) v1(35.94,23.75) v1(36.45,26.16) v1(36.96,24.64) v1(37.34,26.16) v1(38.73,31.11) v1(39.5,30.73) v1(39.62,31.88) v1(39.62,29.72) v1(40.13,32.51) v1(40.89,32) v1(42.04,32) v1(42.8,31.24) v1(42.8,30.35) v1(42.8,29.46) v1(44.32,102.23) v1(44.45,105.92) v1(45.34,105.79) v1(45.34,102.23) v1(45.47,104.78) v1(45.85,101.47) v1(45.85,100.46) v1(45.85,99.57) v1(46.23,106.3) v1(46.86,101.47) v1(46.86,100.46) v1(46.86,99.57) v1(47.12,106.3) v1(47.88,101.47) v1(47.88,100.46) v1(47.88,99.57) v1(49.02,101.47) v1(49.02,100.46) v1(49.02,99.57) v1(50.04,101.47) v1(50.04,100.46) v1(50.04,99.57)
-4.7V: length 13.3
  TOP w0.508: D1.1 v1(27.65,102.14)
  TOP w0.559: TP11.1 14.56,93.01 ; TP11.1 12.36,95.21 ; TP11.1 12.36,93.01 ; TP11.1 14.56,95.21
  PWR2 w0.559: 12.36,93.01 TP11.1 ; TP11.1 14.56,95.21 ; TP11.1 12.36,95.21 ; TP11.1 14.56,93.01
  vias: v1(5.08,93.47) v1(5.08,92.58) v1(5.97,93.47) v1(5.97,92.58) v1(6.99,95.5) v1(6.99,94.49) v1(6.99,93.47) v1(6.99,92.58) v1(19.91,94.9) v1(20,93.91) v1(21.18,92.66) v1(22.6,94.9) v1(22.6,93.83) v1(22.61,92.71) v1(23.75,92.71)
-5V:
  vias: v1(7.62,109.22) v1(7.62,108.46) v1(7.62,107.57) v1(7.62,106.68) v1(7.62,105.54) v1(7.75,104.01) v1(8.26,104.52) v1(8.76,108.46) v1(8.76,107.57) v1(8.76,106.68) v1(9.4,105.79) v1(9.4,105.16)
GND: length 458.5
  TOP w0.178: U1.19 v1(23.37,63.5)
  TOP w0.254: U5.15 27.17,74.69 v1(27.67,75.2) U5.16 ; U4.6 27.12,32.65 v1(27.05,32.59) ; R31.2 23.5,32.51 v1(23.24,32.26) ; U5.14 27.15,74.2 v1(27.65,73.7) U5.13 ; U9.4 v1(10.33,100.12) ; U1.14 v1(25.87,63.46)
  TOP w0.279: U1.12 27.15,61.31 v1(27.69,61.85) ; U1.9 27.74,59.67 arc(27.91,59.64) v1(28.05,59.54) ; U10.8 v1(10.51,82.83) ; v1(19.68,55.12) 20.1,55.53 U1.36 ; U1.17 24.37,62.59 24.42,62.63 24.42,63.09 24.37,63.13 v1(24.37,63.49) ; v1(13.08,87.25) v1(13.08,86.55) 13.08,86.17 12.69,86.17 12.53,86.32 12.53,86.7 v1(12.38,86.55) 11.83,86 U11.15 ; U10.10 v1(11.58,78.33) ; U11.8 v1(13.83,89.78)
  TOP w0.33: v1(18.8,61.59) 19.22,61.17 U1.25 ; U1.1 v1(27.15,55.15)
  TOP w0.381: R85.2 v1(19.43,83.44) ; U7.4 v1(40.68,103.16)
  TOP w0.508: J4.6 v1(43.68,2.42) ; J4.6 v1(44.96,1.01) ; J4.6 v1(44.96,3.93) ; J4.6 v1(46.47,2.42) ; U15.4 v1(36.83,84.96) ; J4.8 v1(36.06,9.39) ; J4.8 v1(34.72,7.92) ; J4.8 v1(37.42,7.92) ; J4.8 v1(36.06,6.36) ; v1(39.62,16) 39.38,15.76 U2.18 ; C48.2 v1(20.83,28.19) ; C48.2 v1(19.3,26.67) ; C48.2 19.3,29.08 v1(18.54,29.84) ; v1(18.8,23.01) v1(18.8,24.51) v1(18.8,26.01) ; U8.4 v1(5.15,111.06) ; U8.4 v1(5.89,111.63) ; U8.4 v1(5.89,110.54) ; C89.2 v1(13.08,102.74) ; v1(12.7,111.51) C84.2 v1(13.72,110.36) ; C87.2 v1(5.59,104.27) 5.46,104.39 C86.2 ; C87.2 v1(5.59,102.36) ; C87.2 v1(4.45,103.38) ; C49.2 v1(15.37,21.72) ; C49.2 v1(14.48,22.61) ; C49.2 v1(16.26,22.61) ; C31.2 v1(29.29,44.24) ; C34.2 v1(41.15,25.78) ; C34.2 v1(41.15,28.45) ; C34.2 v1(39.5,27.18) ; 29.84,27.43 v1(29.84,28.96) ; 29.84,27.43 v1(29.84,26.06) ; 29.84,27.43 v1(31.37,27.43) ; R13.2 v1(11.18,98.17) ; v1(12.32,106.17) C90.2 v1(13.21,105.41) ; C58.2 v1(27.28,82.71) ; v1(41.33,16.18) 41.35,16.17 41.35,14.5 U2.21 ; C33.2 v1(44.58,25.78) ; C33.2 v1(42.93,27.18) ; C33.2 v1(44.58,28.45) ; C78.2 v1(43.43,107.44) ; C78.2 v1(45.59,107.44) ; C78.2 v1(44.45,108.84) ; J4.7 v1(44.96,6.35) ; J4.7 v1(44.96,9.39) ; J4.7 v1(43.61,7.92) ; J4.7 v1(46.31,7.92) ; C25.2 v1(47.82,7.43) ; J4.5 v1(42.11,9.6) ; v1(26.39,29.49) C40.2 v1(25.65,30.1) ; C45.2 v1(29.59,23.24) ; C36.2 v1(39.12,25.4) ; C77.2 v1(41.53,101.98) ; C77.2 v1(40.39,100.84) ; C77.2 v1(41.53,99.82) ; C59.2 v1(18.77,98.4) ; v1(48.39,104.39) C75.2 v1(49.4,105.28) ; C32.2 v1(29.25,49.74) ; R56.1 v1(26.62,109.6) ; C27.2 v1(37.34,12.45) ; 47.12,103.76 v1(47.88,103.76) ; J4.9 v1(37.58,2.42) ; J4.9 v1(36.06,0.89) ; J4.9 v1(34.68,2.42) ; J4.9 v1(36.06,4.19) ; U2.25 v1(43.93,15.86) ; 29.34,24.89 v1(30.23,24.89) ; SW1.1 v1(46.48,92.96) ; C83.1 v1(12.32,108.84) ; C86.2 v1(5.46,106.68) ; C86.2 v1(4.45,105.54) ; C10.2 v1(30.86,60.96) ; C60.2 v1(29.57,82.71) ; R84.2 v1(36.96,103.12) ; R11.2 v1(27.49,81.99) ; U2.7 v1(41.98,22.92) ; C50.2 v1(14.1,25.91) ; U12.2 v1(4.95,89.79) ; C52.2 v1(52.7,108.46) ; C52.2 v1(51.31,109.98) ; C52.2 v1(51.31,106.93) ; SW1.2 v1(46.48,94.23) ; R46.2 v1(23.62,30.35) ; C98.2 v1(20.83,70.48) ; v1(13.46,107.31) C82.2 v1(12.7,108.2) ; C5.2 v1(17.78,76.33) ; R55.2 v1(29.21,109.6) ; v1(24,26.01) v1(24,24.51) v1(24,23.01) 23.47,22.48 C42.2 v1(22.86,21.46) ; C71.2 v1(27.79,71.14) ; C30.2 v1(17.44,49.74) ; C39.2 v1(30.99,29.97) ; C29.2 v1(17.48,44.24) ; Y1.2 v1(46.42,58.99) ; U2.26 v1(44.58,16.12) ; U14.3 v1(46.69,65.71) ; C26.2 v1(38.07,11.53) ; 47.12,102.62 v1(47.88,102.62) ; U13.3 v1(4.53,86.82) ; v1(28.57,35.43) 28.8,35.66 28.8,35.83 28.83,35.86 C38.2 v1(28.07,36.2) ; U14.1 v1(43.35,65.71) ; C35.2 v1(38.86,28.32) ; C46.2 v1(28.96,21.84) ; 36.45,12.06 v1(35.56,12.06) ; C11.2 v1(23.42,95.94) ; C24.2 v1(49.78,8.89) ; C4.2 v1(19.18,74.55) ; C62.2 v1(26.54,110.74)
  TOP w0.559: TP9.1 13.8,36.66 ; TP9.1 11.6,34.46 ; TP9.1 11.6,36.66 ; TP9.1 13.8,34.46 ; 10.46,9.36 TP8.1 ; TP8.1 12.66,7.15 ; TP8.1 12.66,9.36 ; TP8.1 10.46,7.15 ; JP3.2 5.61,82.45 ; JP3.2 4.04,82.45 ; JP3.2 4.04,80.87 ; JP3.2 5.61,80.87 ; TP13.1 45.42,113.07 ; TP13.1 43.22,113.07 ; TP13.1 43.22,115.27 ; TP13.1 45.42,115.27 ; J5.1 5.49,18.64 ; J5.1 3.4,18.64 ; J5.1 3.4,20.73 ; J5.1 5.49,20.73 ; 49.38,73.81 50.16,73.03 ; 50.16,73.03 49.38,72.24 ; 50.16,73.03 50.95,73.81 ; 50.16,73.03 50.95,72.24 ; 52.7,73.03 53.49,73.81 ; 52.7,73.03 53.49,72.24 ; 52.7,73.03 51.92,73.81 ; 52.7,73.03 51.92,72.24 ; 49.38,76.35 50.16,75.56 ; 50.16,75.56 50.95,76.35 ; 50.16,75.56 49.38,74.78 ; 50.16,75.56 50.95,74.78 ; 1.91,19.68 2.69,18.9 ; 1.91,19.68 2.69,20.47 ; 1.91,19.68 1.12,20.47 ; 1.91,19.68 1.12,18.9 ; 41.63,55.91 JP7.2 ; JP7.2 43.21,54.33 ; JP7.2 41.63,54.33 ; JP7.2 43.21,55.91 ; J6.2 50.95,20.47 ; J6.2 49.38,18.9 ; J6.2 50.95,18.9 ; J6.2 49.38,20.47 ; 52.7,75.56 53.49,74.78 ; 52.7,75.56 51.92,74.78 ; 52.7,75.56 53.49,76.35 ; 52.7,75.56 51.92,76.35 ; J6.1 53.75,18.64 ; J6.1 53.75,20.73 ; J6.1 51.66,18.64 ; J6.1 51.66,20.73 ; TP14.1 19.9,104.73 ; TP14.1 17.69,102.53 ; TP14.1 19.9,102.53 ; TP14.1 17.69,104.73
  TOP w0.635: v1(21.17,98.5) 21.17,97.29 C57.2
  GND1 w0.559: 17.69,104.73 TP14.1 ; TP14.1 19.9,102.53 ; TP14.1 19.9,104.73 ; TP14.1 17.69,102.53 ; 52.7,75.56 53.49,74.78 ; 52.7,75.56 51.92,74.78 ; 52.7,75.56 51.92,76.35 ; 52.7,75.56 53.49,76.35 ; 49.38,76.35 50.16,75.56 ; 50.16,75.56 49.38,74.78 ; 50.16,75.56 50.95,74.78 ; 50.16,75.56 50.95,76.35 ; 4.04,82.45 JP3.2 ; JP3.2 5.61,82.45 ; JP3.2 5.61,80.87 ; JP3.2 4.04,80.87 ; 1.91,19.68 2.69,20.47 ; 1.91,19.68 1.12,20.47 ; 1.91,19.68 2.69,18.9 ; 1.91,19.68 1.12,18.9 ; J6.1 53.49,18.9 ; J6.1 51.92,18.9 ; J6.1 51.92,20.47 ; J6.1 53.49,20.47 ; J5.1 5.23,20.47 ; J5.1 3.66,20.47 ; J5.1 5.23,18.9 ; J5.1 3.66,18.9 ; 49.38,72.24 50.16,73.03 ; 50.16,73.03 50.95,73.81 ; 50.16,73.03 50.95,72.24 ; 50.16,73.03 49.38,73.81 ; J6.2 50.95,20.47 ; J6.2 49.38,18.9 ; J6.2 49.38,20.47 ; J6.2 50.95,18.9 ; TP8.1 12.66,9.36 ; TP8.1 10.46,7.15 ; TP8.1 10.46,9.36 ; TP8.1 12.66,7.15 ; 52.7,73.03 53.49,73.81 ; 52.7,73.03 51.92,72.24 ; 52.7,73.03 51.92,73.81 ; 52.7,73.03 53.49,72.24 ; 11.6,34.46 TP9.1 ; TP9.1 11.6,36.66 ; TP9.1 13.8,36.66 ; TP9.1 13.8,34.46 ; 43.22,113.07 TP13.1 ; TP13.1 45.42,113.07 ; TP13.1 43.22,115.27 ; TP13.1 45.42,115.27 ; JP7.2 43.21,55.91 ; JP7.2 41.63,55.91 ; JP7.2 43.21,54.33 ; JP7.2 41.63,54.33
  GND2 w0.559: 17.69,104.73 TP14.1 ; TP14.1 19.9,102.53 ; TP14.1 19.9,104.73 ; TP14.1 17.69,102.53 ; 50.16,75.56 50.95,74.78 ; 50.16,75.56 50.95,76.35 ; 50.16,75.56 49.38,74.78 ; 50.16,75.56 49.38,76.35 ; 10.46,9.36 TP8.1 ; TP8.1 10.46,7.15 ; TP8.1 12.66,9.36 ; TP8.1 12.66,7.15 ; J6.1 53.49,20.47 ; J6.1 53.49,18.9 ; J6.1 51.92,18.9 ; J6.1 51.92,20.47 ; 43.22,113.07 TP13.1 ; TP13.1 45.42,113.07 ; TP13.1 45.42,115.27 ; TP13.1 43.22,115.27 ; 1.12,18.9 1.91,19.68 ; 1.91,19.68 2.69,20.47 ; 1.91,19.68 1.12,20.47 ; 1.91,19.68 2.69,18.9 ; 50.16,73.03 50.95,73.81 ; 50.16,73.03 49.38,72.24 ; 50.16,73.03 50.95,72.24 ; 50.16,73.03 49.38,73.81 ; 11.6,36.66 TP9.1 ; TP9.1 13.8,34.46 ; TP9.1 11.6,34.46 ; TP9.1 13.8,36.66 ; 41.63,54.33 JP7.2 ; JP7.2 43.21,54.33 ; JP7.2 41.63,55.91 ; JP7.2 43.21,55.91 ; 4.04,80.87 JP3.2 ; JP3.2 5.61,82.45 ; JP3.2 4.04,82.45 ; JP3.2 5.61,80.87 ; 52.7,75.56 53.49,76.35 ; 52.7,75.56 51.92,76.35 ; 52.7,75.56 51.92,74.78 ; 52.7,75.56 53.49,74.78 ; 49.38,18.9 J6.2 ; J6.2 50.95,20.47 ; J6.2 50.95,18.9 ; J6.2 49.38,20.47 ; 51.92,72.24 52.7,73.03 ; 52.7,73.03 51.92,73.81 ; 52.7,73.03 53.49,72.24 ; 52.7,73.03 53.49,73.81 ; J5.1 5.23,20.47 ; J5.1 5.23,18.9 ; J5.1 3.66,20.47 ; J5.1 3.66,18.9
  BOTTOM w0.33: v1(28.7,50.74) 28.2,51.24 U3.4 ; v1(28.32,53.21) 27.85,52.74 U3.1 ; U3.10 v1(28.3,48.24) ; U3.20 v1(28.39,43.24) ; U3.34 v1(18.31,45.74) ; v1(28.57,42.55) 28.27,42.24 U3.22 ; U3.19 28.78,43.74 v1(29.34,43.18) ; U3.21 v1(25.85,42.74) ; U3.39 v1(18.44,48.24) ; U3.28 v1(18.09,42.74) ; U3.15 v1(25.8,45.74) ; U3.24 v1(25.94,41.24) ; U3.45 v1(18.35,51.24)
  BOTTOM w0.508: 21.21,60.83 C17.2 21.84,60.6 v2(21.64,60.4) 21.21,60.83 ; 21.21,60.83 C16.2 ; R32.2 v1(30.23,54.36) ; C14.2 24.18,60.83 v2(24.61,60.4) ; C61.2 v1(43.81,89.53) ; C19.2 21.34,56.13 v2(21.64,56.44) ; C102.2 v1(8.13,84.84) ; v2(25.6,60.4) 25.88,60.68 C21.2 ; v2(22.63,60.4) 22.99,60.76 C18.2 ; 10.03,88.9 v1(10.03,89.51) ; 19.56,61.85 v1(19.56,62.74) ; 16,78.87 v1(16,79.5) ; C101.2 v1(10.16,84.45) ; v2(25.6,59.41) 25.83,59.18 C13.2 ; C51.2 v1(11.56,81.03) ; v2(25.6,56.44) 25.91,56.13 C20.2 ; C28.2 v1(40.41,16.03) ; 14.86,78.87 v1(14.86,79.38) ; C9.1 v1(42.29,68.33) ; 10.03,90.81 v1(10.03,90.17) ; C12.2 v1(38.23,61.47) ; C22.2 v1(15.24,81.03)
  BOTTOM w0.559: 49.38,20.47 J6.2 ; J6.2 50.95,20.47 ; J6.2 50.95,18.9 ; J6.2 49.38,18.9 ; 41.63,55.91 JP7.2 41.63,54.33 ; JP3.2 5.61,80.87 ; JP3.2 5.61,82.45 ; JP3.2 4.04,80.87 ; J5.1 5.49,18.64 ; J5.1 5.49,20.73 ; J5.1 3.4,18.64 ; J5.1 3.4,20.73 ; 17.69,102.53 TP14.1 ; TP14.1 17.69,104.73 ; TP14.1 19.9,104.73 ; TP14.1 19.9,102.53 ; 52.7,71.98 52.7,74.07 ; J6.1 53.75,18.64 ; J6.1 51.66,18.64 ; J6.1 51.66,20.73 ; J6.1 53.75,20.73 ; 43.22,113.07 TP13.1 ; TP13.1 45.42,113.07 ; TP13.1 45.42,115.27 ; TP13.1 43.22,115.27 ; 10.46,9.36 TP8.1 ; TP8.1 10.46,7.15 ; TP8.1 12.66,9.36 ; TP8.1 12.66,7.15 ; 1.12,20.47 1.91,19.68 ; 1.91,19.68 2.69,20.47 ; 1.91,19.68 1.12,18.9 ; 1.91,19.68 2.69,18.9 ; 50.16,71.98 50.16,74.07 ; 52.7,76.61 52.7,74.52 ; 11.6,34.46 TP9.1 ; TP9.1 11.6,36.66 ; TP9.1 13.8,36.66 ; TP9.1 13.8,34.46 ; 50.16,76.61 50.16,74.52
  vias: v1(0.76,43.31) v1(0.76,40.77) v1(0.76,18.16) v1(0.76,15.62) v1(0.76,13.46) v1(0.76,10.92) v1(0.76,9.02) v1(0.76,6.48) v1(0.89,117.22) v1(0.89,114.68) v1(0.89,112.14) v1(0.89,111) v1(0.89,109.6) v1(0.89,92.84) v1(0.89,90.3) v1(0.89,84.96) v1(0.89,82.42) v1(0.89,79.38) v1(0.89,76.83) v1(0.89,74.17) v1(0.89,71.63) v1(0.89,69.22) v1(0.89,66.67) v1(0.89,63.88) v1(0.89,61.34) v1(0.89,59.05) v1(0.89,56.52) v1(0.89,38.61) v1(0.89,36.07) v1(0.89,33.53) v1(0.89,30.99) v1(0.89,28.45) v1(0.89,25.91) v1(0.89,23.5) v1(0.89,20.95) v1(1.02,120.52) v1(1.02,116.08) v1(1.02,100.2) v1(1.27,106.05) v1(1.27,103.5) v1(1.27,96.52) v1(1.27,93.98) v1(1.27,89.53) v1(1.27,87) v1(1.27,80.77) v1(1.27,9.53) v1(1.27,6.99) v1(2.03,6.48) v1(2.16,112.27) v1(2.16,109.73) v1(2.29,121.79) v1(2.29,119.25) v1(2.29,117.35) v1(2.29,114.81) v1(2.29,101.47) v1(2.29,98.93) v1(2.54,104.78) v1(2.54,95.25) v1(2.54,88.27) v1(2.54,8.26) v1(3.68,122.05) v1(3.81,106.05) v1(3.81,103.5) v1(3.81,96.52) v1(3.81,93.98) v1(3.81,89.53) v1(3.81,87) v1(3.81,9.53) v1(3.81,6.99) v1(4.57,6.48) v1(5.33,6.48) v1(5.71,17.14) v1(5.71,14.61) v1(5.71,12.06) v1(5.71,9.53) v1(6.22,122.05) v1(6.22,52.2) v1(6.22,49.66) v1(6.22,47.12) v1(6.86,76.45) v1(6.99,21.59) v1(6.99,19.05) v1(6.99,15.88) v1(6.99,10.79) v1(7.11,102.23) v1(7.49,50.93) v1(7.62,121.28) v1(7.62,118.75) v1(7.62,30.48) v1(7.62,27.94) v1(7.87,6.48) v1(8,48.01) v1(8,45.47) v1(8.26,20.32) v1(8.26,17.14) v1(8.26,14.61) v1(8.26,12.06) v1(8.26,9.53) v1(8.89,120.02) v1(8.89,117.47) v1(8.89,114.94) v1(8.89,29.21) v1(8.89,26.04) v1(8.89,23.5) v1(9.02,49.4) v1(9.53,21.59) v1(9.53,19.05) v1(9.91,6.48) v1(10.03,48.26) v1(10.16,121.28) v1(10.16,118.75) v1(10.16,116.2) v1(10.16,30.48) v1(10.16,27.94) v1(10.16,24.77) v1(10.16,15.88) v1(10.16,13.34) v1(10.79,75.31) v1(11.3,47.12) v1(11.43,117.47) v1(11.43,114.94) v1(11.43,26.04) v1(11.43,23.5) v1(11.43,20.32) v1(11.43,17.78) v1(11.43,14.61) v1(11.56,122.05) v1(11.56,102.23) v1(11.56,57.53) v1(11.81,72.01) v1(11.81,45.47) v1(12.38,87.95) v1(12.38,87.25) v1(12.45,6.48) v1(12.7,121.28) v1(12.7,118.75) v1(12.7,19.05) v1(12.7,15.88) v1(12.7,13.34) v1(13.08,87.95) v1(13.34,100.97) v1(13.34,98.42) v1(13.72,59.31) v1(13.78,87.95) v1(13.78,87.25) v1(13.78,86.55) v1(13.84,56.39) v1(13.84,55.24) v1(13.97,120.02) v1(13.97,117.47) v1(13.97,114.94) v1(13.97,20.32) v1(13.97,17.78) v1(14.1,122.05) v1(14.61,99.69) v1(14.61,47.5) v1(14.73,55.75) v1(14.99,18.67) v1(14.99,16.13) v1(14.99,13.34) v1(14.99,10.79) v1(14.99,9.02) v1(14.99,6.48) v1(15.24,121.28) v1(15.24,118.75) v1(15.24,116.2) v1(15.24,113.67) v1(15.24,111.12) v1(15.62,56.13) v1(15.62,55.24) v1(15.75,47.37) v1(15.88,100.97) v1(15.88,98.42) v1(15.88,57.78) v1(15.88,21.21) v1(16.26,122.05) v1(16.51,117.47) v1(16.51,114.94) v1(16.51,112.39) v1(16.51,104.78) v1(16.51,102.23) v1(16.76,120.02) v1(17.65,116.2) v1(17.65,57.91) v1(17.78,113.67) v1(17.78,111.12) v1(17.78,108.58) v1(17.78,106.05) v1(18.03,121.28) v1(18.03,118.75) v1(18.03,61.47) v1(18.16,62.36) v1(18.41,21.21) v1(18.8,122.05) v1(18.92,117.47) v1(18.92,114.94) v1(18.92,62.48) v1(18.92,55.24) v1(19.05,112.39) v1(19.05,109.86) v1(19.05,107.31) v1(19.05,57.91) v1(19.81,77.85) v1(19.94,79.63) v1(20.07,121.67) v1(20.07,119.89) v1(20.07,118.24) v1(20.07,54.74) v1(20.19,116.2) v1(20.32,111.12) v1(20.32,108.58) v1(20.32,106.05) v1(20.83,81.03) v1(21.34,82.68) v1(21.46,117.47) v1(21.46,114.94) v1(21.59,112.39) v1(21.59,109.86) v1(22.23,47.37) v1(22.23,44.83) v1(22.61,69.34) v1(22.61,67.56) v1(22.86,66.29) v1(22.86,64.77) v1(22.99,108.2) v1(22.99,106.55) v1(22.99,104.9) v1(22.99,100.97) v1(22.99,99.06) v1(22.99,97.03) v1(23.37,121.79) v1(23.37,120.02) v1(23.37,118.36) v1(23.37,85.47) v1(23.37,83.95) v1(23.5,110.11) v1(23.5,102.87) v1(23.62,116.33) v1(23.62,114.55) v1(23.62,112.78) v1(23.62,82.3) v1(24.68,74.9) v1(24.68,73.99) v1(25.14,74.45) v1(25.59,74.9) v1(25.59,73.99) v1(26.42,116.33) v1(26.42,114.55) v1(26.42,84.96) v1(26.54,121.79) v1(26.54,120.02) v1(26.54,118.36) v1(26.92,108.08) v1(26.92,106.43) v1(26.92,104.78) v1(26.92,100.84) v1(26.92,98.93) v1(26.92,96.9) v1(27.05,32.03) v1(27.05,31.47) v1(27.3,75.69) v1(27.3,66.29) v1(27.3,64.77) v1(27.3,62.23) v1(27.43,54.23) v1(27.56,69.34) v1(27.56,67.56) v1(27.69,74.42) v1(27.94,96.01) v1(27.94,62.87) v1(28.07,55.12) v1(28.32,61.98) v1(28.45,93.47) v1(28.57,82.42) v1(28.57,45.72) v1(28.7,75.95) v1(28.83,47.24) v1(29.08,55.63) v1(29.21,99.69) v1(29.21,97.16) v1(29.59,76.58) v1(29.72,80.9) v1(29.72,78.23) v1(29.84,115.7) v1(29.84,113.67) v1(29.84,111.12) v1(29.97,121.67) v1(29.97,119.89) v1(29.97,118.24) v1(29.97,40.89) v1(30.1,58.93) v1(30.23,61.59) v1(30.48,98.42) v1(30.48,75.56) v1(30.48,73.03) v1(30.61,93.34) v1(30.61,79.63) v1(30.82,95.43) v1(30.86,87.5) v1(30.86,21.21) v1(30.99,62.36) v1(31.11,116.97) v1(31.11,114.43) v1(31.11,112.39) v1(31.75,121.92) v1(31.75,120.14) v1(31.75,99.69) v1(31.75,97.16) v1(31.75,74.3) v1(31.75,65.28) v1(32.13,59.05) v1(32.26,93.6) v1(32.38,113.67) v1(32.38,111.12) v1(33.02,118.75) v1(33.02,116.2) v1(33.02,75.56) v1(33.02,73.03) v1(33.15,81.53) v1(33.27,58.93) v1(33.4,92.58) v1(33.4,87.5) v1(33.4,21.21) v1(33.66,68.07) v1(33.78,69.85) v1(33.78,66.67) v1(33.91,90.3) v1(33.91,63.5) v1(33.91,61.34) v1(34.04,78.61) v1(34.16,71.75) v1(34.29,121.92) v1(34.29,120.14) v1(34.29,117.47) v1(34.29,112.39) v1(34.29,109.86) v1(34.54,12.83) v1(34.54,10.29) v1(34.54,6.35) v1(34.54,3.81) v1(34.92,19.05) v1(34.92,16.51) v1(35.56,118.75) v1(35.56,116.2) v1(35.56,111.12) v1(35.56,73.15) v1(35.56,66.04) v1(35.56,64.26) v1(36.2,82.8) v1(36.2,17.78) v1(36.32,62.48) v1(36.58,121.92) v1(36.58,70.23) v1(36.7,105.41) v1(36.7,104.01) v1(36.83,117.47) v1(36.83,114.94) v1(36.83,112.39) v1(36.83,109.86) v1(37.21,108.46) v1(37.21,107.06) v1(37.21,78.36) v1(37.34,74.93) v1(37.47,19.05) v1(37.47,16.51) v1(37.59,65.41) v1(37.72,73.66) v1(38.1,116.2) v1(38.1,113.67) v1(38.1,111.12) v1(38.1,80.01) v1(38.1,70.87) v1(38.1,0.89) v1(38.48,24) v1(38.73,66.42) v1(39.12,121.92) v1(39.37,117.47) v1(39.37,114.94) v1(39.37,112.39) v1(39.37,76.2) v1(39.62,103.25) v1(39.62,70.36) v1(39.75,82.93) v1(40.26,77.85) v1(40.26,73.66) v1(40.64,118.75) v1(40.64,116.2) v1(40.64,113.67) v1(40.64,111.12) v1(40.64,0.89) v1(41.22,74.3) v1(41.91,121.92) v1(41.91,120.14) v1(41.91,117.47) v1(42.29,73.66) v1(42.42,77.72) v1(42.42,76.07) v1(42.67,79.38) v1(42.8,66.67) v1(42.8,64.64) v1(42.8,62.36) v1(42.93,106.43) v1(42.93,101.85) v1(43.18,118.75) v1(43.18,116.2) v1(43.18,111.12) v1(43.18,81.15) v1(43.43,61.09) v1(43.94,83.44) v1(44.2,71.37) v1(44.32,119.13) v1(44.45,121.92) v1(44.45,117.47) v1(44.45,112.39) v1(44.58,82.68) v1(45.09,19.68) v1(45.09,17.14) v1(45.34,37.21) v1(45.59,79.25) v1(45.59,74.3) v1(45.59,73.53) v1(45.72,116.2) v1(45.72,111.12) v1(45.72,77.6) v1(45.72,75.95) v1(46.1,83.44) v1(46.1,38.23) v1(46.35,18.41) v1(46.61,80.64) v1(46.61,66.67) v1(46.74,72.77) v1(46.74,0.89) v1(46.86,119.13) v1(46.86,61.09) v1(46.86,26.16) v1(46.99,117.47) v1(46.99,114.94) v1(47.24,64.26) v1(47.24,62.36) v1(47.5,71.25) v1(47.5,69.34) v1(47.5,66.93) v1(47.62,19.68) v1(47.62,17.14) v1(48.26,122.05) v1(48.26,36.07) v1(48.51,80.77) v1(48.64,83.57) v1(49.28,0.89) v1(49.4,90.81) v1(49.53,114.3) v1(49.53,111.76) v1(50.29,83.82) v1(50.29,80.52) v1(50.8,122.05) v1(50.8,113.03) v1(50.8,8.26) v1(50.8,5.71) v1(50.8,3.81) v1(50.8,1.27) v1(50.93,91.57) v1(52.07,114.3) v1(52.07,111.76) v1(52.07,80.52) v1(52.07,6.99) v1(52.07,2.54) v1(52.2,83.82) v1(53.34,8.26) v1(53.34,5.71) v1(53.34,3.81) v1(53.34,1.27) v1(53.72,121.67) v1(53.72,119.13) v1(53.72,116.59) v1(53.72,114.05) v1(53.72,111.51) v1(53.72,108.97) v1(53.72,106.3) v1(53.72,103.76) v1(53.72,100.97) v1(53.72,98.42) v1(53.72,95.5) v1(53.72,92.96) v1(53.72,89.92) v1(53.72,87.38) v1(53.72,83.82) v1(53.72,80.52) v1(53.72,18.03) v1(53.72,15.49) v1(53.72,12.95) v1(53.72,10.41) v2(8.76,102.74) v2(8.76,101.74) v2(9.36,102.24) v2(9.96,102.74) v2(9.96,101.74) v2(21.64,59.41) v2(21.64,58.42) v2(21.64,57.43) v2(22.63,59.41) v2(22.63,58.42) v2(22.63,57.43) v2(22.63,56.44) v2(23.62,60.4) v2(23.62,59.41) v2(23.62,58.42) v2(23.62,57.43) v2(23.62,56.44) v2(24.61,59.41) v2(24.61,58.42) v2(24.61,57.43) v2(24.61,56.44) v2(25.6,58.42) v2(25.6,57.43) v2(42.43,104.74) v2(42.43,103.54) v2(42.93,104.14) v2(43.43,104.74) v2(43.43,103.54) v3(51.05,85.34) v3(51.05,84.58) v3(51.05,79.76) v3(51.05,78.99) v3(51.82,85.34) v3(51.82,84.58) v3(51.82,79.76) v3(51.82,78.99) v3(52.58,85.34) v3(52.58,84.58) v3(52.58,79.76) v3(52.58,78.99) v3(53.34,85.34) v3(53.34,84.58) v3(53.34,79.76) v3(53.34,78.99) v3(54.1,85.34) v3(54.1,84.58) v3(54.1,79.76) v3(54.1,78.99)
